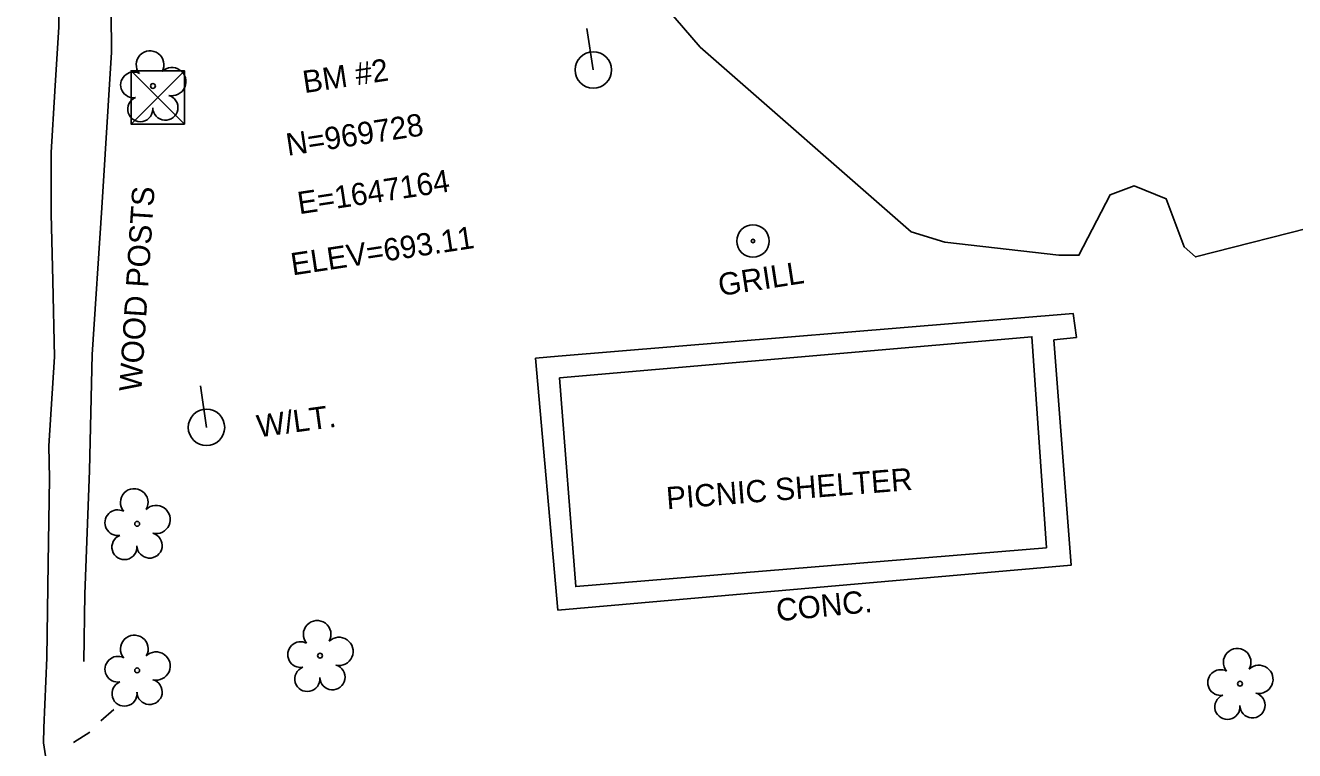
# Model space of a CAD drawing. Extents: x 1645945 to 2447332, y 713118 to 970361.
# Drawn here: x 1647146.3 to 1647317.1, y 969639.7 to 969737.2 of the extents above; entities that cross this region are included whole.
import ezdxf

# ---------------------------------------------------------------- set-up
doc = ezdxf.new("R2010")
doc.units = 0
for name, color, linetype in [('CTL Vertical Benchmark CELL', 7, 'Continuous'), ('CTL Vertical Benchmark Text', 7, 'Continuous'), ('Exist Building', 7, 'Continuous'), ('Exist Building Text', 7, 'Continuous'), ('Exist Horizontal Alignment', 7, 'Continuous'), ('Exist Other Culture Area Outline', 7, 'Continuous'), ('Exist Other Culture Area Outline Text', 7, 'Continuous'), ('Exist Other Culture Fence Line', 7, 'Continuous'), ('Exist Other Culture Fence Line Text', 7, 'Continuous'), ('Exist Other Culture Located Object CELL', 7, 'Continuous'), ('Exist Other Culture Located Object Text', 7, 'Continuous'), ('Exist Other Culture Sign CELL', 7, 'Continuous'), ('Exist Right of Way Line', 7, 'Continuous'), ('Exist Roads EOP', 7, 'Continuous'), ('Exist Roads EOP Other', 7, 'Continuous'), ('Exist Utilities Power Pole CELL', 7, 'Continuous'), ('Exist Utilities Power Pole Text', 7, 'Continuous'), ('Exist Vegetation Tree CELL', 7, 'Continuous'), ('Exist Vegetation Woods Line', 7, 'Continuous')]:
    doc.layers.add(name, color=color, linetype=linetype)

msp = doc.modelspace()

# ---------------------------------------------------------------- linework, layer by layer
at = {"layer": 'CTL Vertical Benchmark CELL'}
msp.add_line((1647164.14, 969727.55), (1647164.14, 969727.55), dxfattribs=at)
msp.add_line((1647164.14, 969727.55), (1647164.14, 969727.55), dxfattribs=at)
msp.add_lwpolyline([(1647160.54, 969731.14), (1647167.73, 969731.14), (1647167.73, 969723.95), (1647160.54, 969723.95)], close=True, dxfattribs=at)
msp.add_lwpolyline([(1647160.54, 969731.14), (1647167.73, 969731.14), (1647167.73, 969723.95), (1647160.54, 969723.95)], close=True, dxfattribs=at)
for points in [[(1647167.73, 969731.14), (1647160.54, 969723.95), (1647164.14, 969727.55), (1647167.73, 969723.95), (1647160.54, 969731.14)], [(1647164.14, 969727.55), (1647167.73, 969731.14), (1647160.54, 969731.14), (1647164.14, 969727.55)], [(1647167.73, 969731.14), (1647160.54, 969723.95), (1647164.14, 969727.55), (1647167.73, 969723.95), (1647160.54, 969731.14)], [(1647164.14, 969727.55), (1647167.73, 969731.14), (1647160.54, 969731.14), (1647164.14, 969727.55)], [(1647164.14, 969727.55), (1647160.54, 969723.95), (1647167.73, 969723.95), (1647164.14, 969727.55)], [(1647164.14, 969727.55), (1647160.54, 969723.95), (1647167.73, 969723.95), (1647164.14, 969727.55)]]:
    msp.add_lwpolyline(points, dxfattribs=at)
at = {"layer": 'Exist Building'}
msp.add_lwpolyline([(1647218.17, 969689.81), (1647220.37, 969661.73), (1647283.72, 969666.96), (1647281.76, 969695.34)], close=True, dxfattribs=at)
at = {"layer": 'Exist Horizontal Alignment'}
msp.add_arc((1647013.36, 970445.89), 900, 278.18107, 298.87121, dxfattribs=at)
at = {"layer": 'Exist Other Culture Area Outline'}
msp.add_lwpolyline([(1647284.72, 969694.92), (1647287.05, 969664.64), (1647245.61, 969660.99), (1647217.98, 969658.58), (1647214.98, 969692.46), (1647218.03, 969692.74), (1647287.32, 969698.47), (1647287.75, 969695.25)], close=True, dxfattribs=at)
at = {"layer": 'Exist Other Culture Fence Line'}
msp.add_lwpolyline([(1647158.47, 969767.25), (1647158.47, 969767.24), (1647157.76, 969749.69), (1647157.9, 969733.64), (1647156.59, 969712.7), (1647155.3, 969692.94), (1647154.95, 969677.36), (1647154.34, 969660.7), (1647154.18, 969651.66)], dxfattribs=at)
at = {"layer": 'Exist Other Culture Located Object CELL'}
for radius in [2.18, 0.24]:
    msp.add_circle((1647244.22, 969708.22), radius, dxfattribs=at)
at = {"layer": 'Exist Other Culture Sign CELL'}
for p, q in [((1647156.46, 969643.66), (1647158.21, 969645.21)), ((1647152.79, 969640.77), (1647154.98, 969642.15))]:
    msp.add_line(p, q, dxfattribs=at)
at = {"layer": 'Exist Right of Way Line'}
msp.add_arc((1647025.62, 970422.4), 845, 278.18107, 299.46236, dxfattribs=at)
at = {"layer": 'Exist Roads EOP'}
for points in [[(1647712.71, 969946.05), (1647689.83, 969906.56), (1647665.85, 969869.13), (1647637.34, 969829.12), (1647607.92, 969794.57), (1647574.53, 969760.72), (1647538.69, 969730.5), (1647499.85, 969702.79), (1647457.34, 969676.33), (1647411.66, 969651.37), (1647366.8, 969630.41), (1647321.37, 969611.83), (1647279.28, 969597.97), (1647224.82, 969583.15), (1647179.92, 969574.15), (1647132.17, 969565.53), (1647083.22, 969557.97), (1647036.22, 969550.58), (1646989.26, 969543.73)], [(1647731.3, 969935.45), (1647707.71, 969895.07), (1647684.27, 969857.13), (1647654.38, 969814.5), (1647624.46, 969779.25), (1647589.97, 969744.66), (1647553.5, 969714.01), (1647512.43, 969684.95), (1647469.3, 969658.19), (1647421.26, 969632.07), (1647375.68, 969609.9), (1647329.15, 969590.49), (1647286.02, 969576.26), (1647230.19, 969561.18), (1647183.04, 969552.75), (1647135.89, 969544.58), (1647086.4, 969536.99), (1647040.14, 969529.53), (1646992.05, 969522.32)]]:
    msp.add_spline(points, degree=3, dxfattribs=at)
at = {"layer": 'Exist Roads EOP Other'}
msp.add_lwpolyline([(1647150.73, 969745.46), (1647150.83, 969737.05), (1647150.26, 969728.39), (1647149.78, 969720.15), (1647149.8, 969711.87), (1647150.02, 969702.89), (1647150.22, 969692.64), (1647149.49, 969680.66), (1647149.57, 969676.27), (1647149.4, 969664.9), (1647149.19, 969652.14), (1647148.8, 969642.73), (1647148.77, 969640.73), (1647149.01, 969638.95)], dxfattribs=at)
at = {"layer": 'Exist Utilities Power Pole CELL'}
for p, q in [((1647222.74, 969731.24), (1647221.89, 969736.8)), ((1647222.74, 969731.24), (1647222.74, 969731.24)), ((1647170.69, 969683.16), (1647169.89, 969688.73)), ((1647170.69, 969683.16), (1647170.69, 969683.16))]:
    msp.add_line(p, q, dxfattribs=at)
for centre in [(1647222.74, 969731.24), (1647170.69, 969683.16)]:
    msp.add_circle(centre, 2.45, dxfattribs=at)
at = {"layer": 'Exist Vegetation Tree CELL'}
for p, q in [((1647163.48, 969729.08), (1647163.48, 969729.08)), ((1647161.36, 969670.17), (1647161.36, 969670.17)), ((1647185.97, 969652.44), (1647185.97, 969652.44)), ((1647161.36, 969650.46), (1647161.36, 969650.46)), ((1647309.76, 969648.67), (1647309.76, 969648.67))]:
    msp.add_line(p, q, dxfattribs=at)
for centre in [(1647163.48, 969729.08), (1647161.36, 969670.17), (1647185.97, 969652.44), (1647161.36, 969650.46), (1647309.76, 969648.67)]:
    msp.add_circle(centre, 0.326, dxfattribs=at)
for centre, radius, start, end in [((1647163.09, 969731.95), 1.86, 330.1651, 219.7134), ((1647160.87, 969729.23), 1.73, 62.6636, 279.3457), ((1647166.03, 969729.67), 1.9, 257.1011, 134.1999), ((1647161.77, 969725.96), 1.69, 111.5671, 6.231), ((1647165.15, 969726.18), 1.7, 181.2822, 74.56), ((1647160.97, 969673.05), 1.86, 330.1651, 219.7134), ((1647158.75, 969670.33), 1.73, 62.6636, 279.3457), ((1647163.91, 969670.76), 1.9, 257.1011, 134.1999), ((1647159.65, 969667.05), 1.69, 111.5671, 6.231), ((1647163.03, 969667.27), 1.7, 181.2822, 74.56), ((1647185.58, 969655.31), 1.86, 330.1651, 219.7134), ((1647160.98, 969653.34), 1.86, 330.1651, 219.7134), ((1647183.36, 969652.59), 1.73, 62.6636, 279.3457), ((1647188.52, 969653.02), 1.9, 257.1011, 134.1999), ((1647158.76, 969650.62), 1.73, 62.6636, 279.3457), ((1647163.91, 969651.05), 1.9, 257.1011, 134.1999), ((1647309.38, 969651.55), 1.86, 330.1651, 219.7134), ((1647184.26, 969649.31), 1.69, 111.5671, 6.231), ((1647187.64, 969649.54), 1.7, 181.2822, 74.56), ((1647312.31, 969649.26), 1.9, 257.1011, 134.1999), ((1647163.03, 969647.57), 1.7, 181.2822, 74.56), ((1647307.16, 969648.83), 1.73, 62.6636, 279.3457), ((1647159.66, 969647.34), 1.69, 111.5671, 6.231), ((1647311.43, 969645.77), 1.7, 181.2822, 74.56), ((1647308.06, 969645.55), 1.69, 111.5671, 6.231)]:
    msp.add_arc(centre, radius, start, end, dxfattribs=at)
at = {"layer": 'Exist Vegetation Woods Line'}
msp.add_lwpolyline([(1647517.03, 969744.5), (1647495.35, 969729.99), (1647471.19, 969716.25), (1647460.39, 969710.38), (1647431.64, 969709.61), (1647415.55, 969712.4), (1647401.93, 969713.9), (1647395.29, 969716.09), (1647374.09, 969725.56), (1647339.04, 969715.08), (1647303.79, 969706.09), (1647302.25, 969707.44), (1647299.84, 969713.9), (1647295.54, 969715.64), (1647292.3, 969714.45), (1647288.08, 969706.3), (1647285.4, 969706.33), (1647270.06, 969708.07), (1647265.52, 969709.48), (1647237.13, 969734.31), (1647228.98, 969743.77)], dxfattribs=at)

# ---------------------------------------------------------------- texts
at = {"layer": 'CTL Vertical Benchmark Text'}
for s, p in [('BM #2', (1647183.87, 969728.11)), ('N=969728', (1647181.63, 969719.68)), ('E=1647164', (1647183.17, 969711.82)), ('ELEV=693.11', (1647182.27, 969703.59))]:
    msp.add_text(s, height=3, rotation=8.5829, dxfattribs=at).set_placement(p)
at = {"layer": 'Exist Building Text'}
msp.add_text('PICNIC SHELTER', height=3, rotation=4.5363, dxfattribs=at).set_placement((1647232.67, 969672.12))
at = {"layer": 'Exist Other Culture Area Outline Text'}
msp.add_text('CONC.', height=3, rotation=5.6984, dxfattribs=at).set_placement((1647247.5, 969657.05))
at = {"layer": 'Exist Other Culture Fence Line Text'}
msp.add_text('WOOD POSTS', height=3, rotation=86.2643, dxfattribs=at).set_placement((1647161.92, 969687.9))
at = {"layer": 'Exist Other Culture Located Object Text'}
msp.add_text('GRILL', height=3, rotation=8.7749, dxfattribs=at).set_placement((1647239.79, 969700.81))
at = {"layer": 'Exist Utilities Power Pole Text'}
msp.add_text('W/LT.', height=3, rotation=7.7882, dxfattribs=at).set_placement((1647177.67, 969681.8))

doc.saveas('drawing.dxf')
